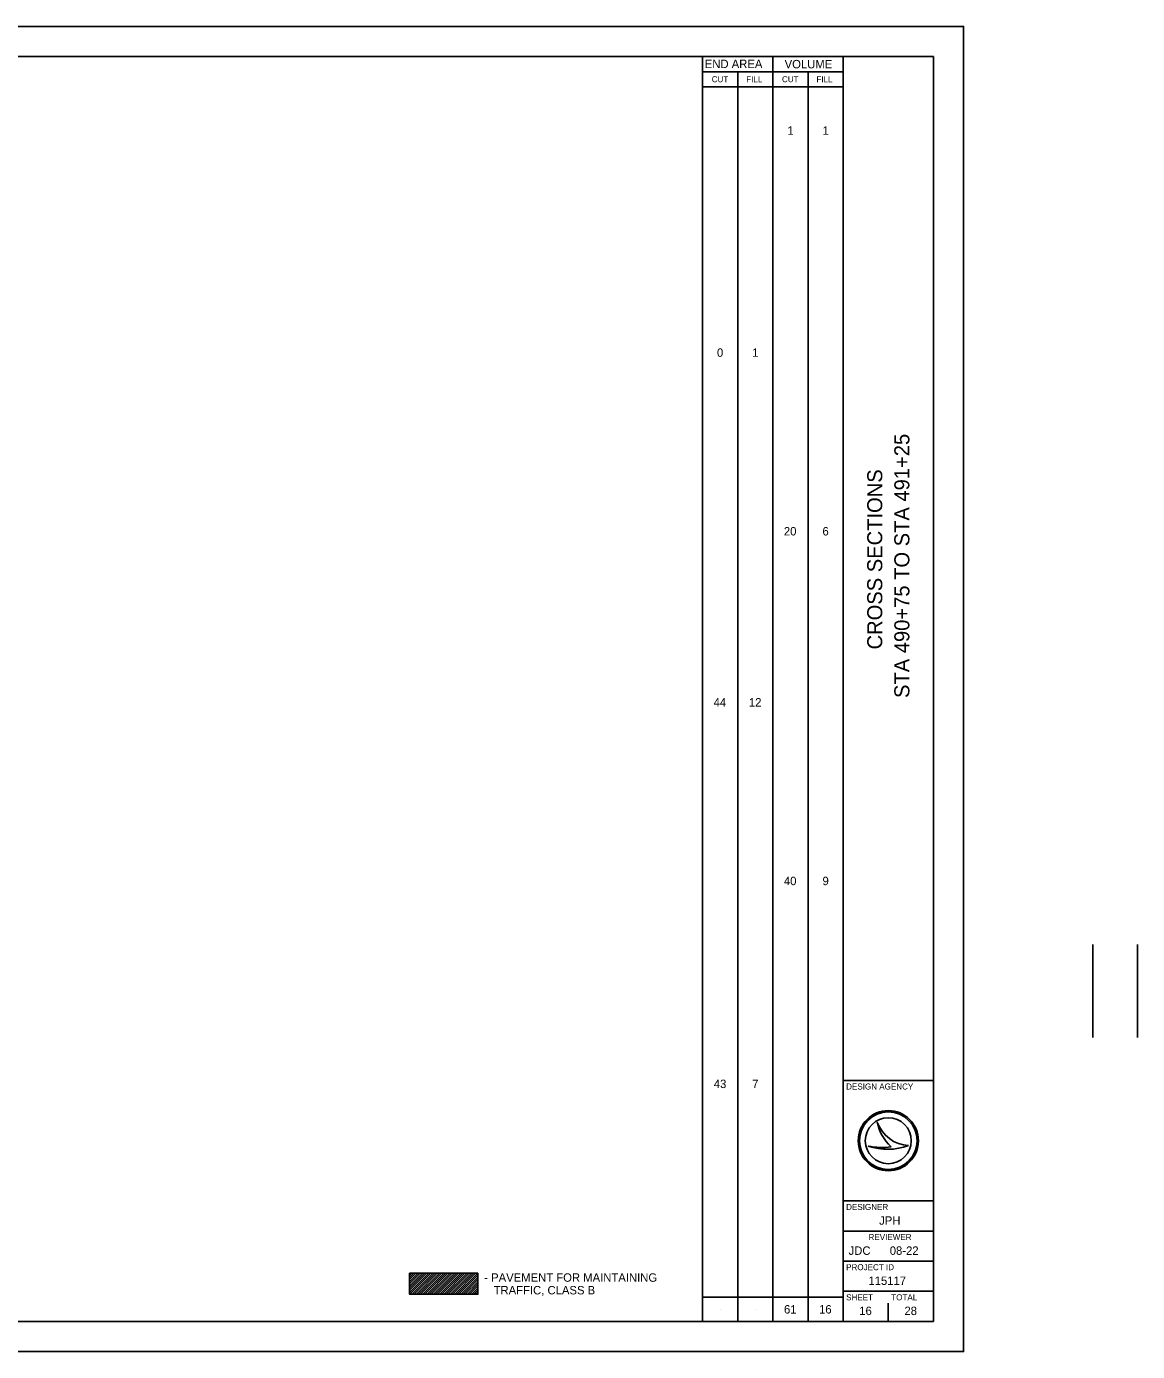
# Model space of a CAD drawing. Extents: x -78 to 37, y -177 to 22.
# Drawn here: x 18.44 to 36.89, y 0 to 22 of the extents above; entities that cross this region are included whole.
import ezdxf

# ---------------------------------------------------------------- set-up
doc = ezdxf.new("R2010")
doc.units = 0
for name, color, linetype in [('GE_X_Alignment_500_Curve_Data', 7, 'Continuous'), ('RW_P_Esmt_SH', 7, 'Continuous'), ('RW_X_Esmt_SH', 7, 'Continuous'), ('SH_Border', 7, 'Continuous'), ('SH_Cut_Line', 7, 'Continuous'), ('SH_Data', 7, 'Continuous'), ('TX_P_1', 7, 'Continuous'), ('TX_P_10', 7, 'Continuous')]:
    doc.layers.add(name, color=color, linetype=linetype)

msp = doc.modelspace()

# ---------------------------------------------------------------- linework, layer by layer
at = {"layer": 'RW_P_Esmt_SH'}
msp.add_line((36.143, 5.216), (36.143, 6.758), dxfattribs=at)
at = {"layer": 'RW_X_Esmt_SH'}
msp.add_line((36.887, 5.216), (36.887, 6.758), dxfattribs=at)
at = {"layer": 'SH_Border'}
for p, q in [((32, 0.5), (32, 21.5)), ((32, 4.5), (33.5, 4.5)), ((32, 2.5), (33.5, 2.5)), ((32, 2), (33.5, 2)), ((32, 1.5), (33.5, 1.5)), ((32, 1), (33.5, 1))]:
    msp.add_line(p, q, dxfattribs=at)
msp.add_lwpolyline([(1.5, 21.5), (33.5, 21.5), (33.5, 0.5), (1.5, 0.5)], close=True, dxfattribs=at)
at = {"layer": 'SH_Cut_Line'}
msp.add_lwpolyline([(0, 0), (34, 0), (34, 22), (0, 22)], close=True, dxfattribs=at)
at = {"layer": 'SH_Data'}
for p, q in [((29.666, 0.5), (29.666, 21.5)), ((30.833, 0.5), (30.833, 21.5)), ((29.666, 21.25), (32, 21.25)), ((30.25, 0.5), (30.25, 21.25)), ((31.417, 0.5), (31.417, 21.25)), ((29.666, 21), (32, 21)), ((32.567, 3.81), (32.567, 3.81)), ((32.417, 3.41), (32.417, 3.41)), ((32.75, 3.5), (32.75, 3.5)), ((33.087, 3.419), (33.087, 3.419)), ((29.666, 0.9), (32, 0.9)), ((29.958, 0.7), (29.958, 0.7)), ((30.542, 0.7), (30.542, 0.7)), ((31.125, 0.7), (31.125, 0.7)), ((31.708, 0.7), (31.708, 0.7)), ((32.375, 0.675), (32.375, 0.675)), ((32.75, 0.5), (32.75, 0.8))]:
    msp.add_line(p, q, dxfattribs=at)
for radius in [0.5, 0.477, 0.477, 0.382]:
    msp.add_circle((32.75, 3.5), radius, dxfattribs=at)
for centre, radius, start, end in [((33.116, 3.998), 0.58, 198.9257, 198.9319), ((33.347, 3.97), 0.796, 191.6379, 191.6421), ((33.116, 3.998), 0.58, 198.9319, 267.1657), ((33.347, 3.97), 0.796, 191.6421, 226.0947), ((32.739, 4.37), 1.013, 251.4576, 290.0832), ((32.648, 4.654), 1.266, 259.4964, 259.4995), ((32.739, 4.37), 1.013, 251.4527, 251.4576), ((32.648, 4.654), 1.266, 259.4995, 276.6672)]:
    msp.add_arc(centre, radius, start, end, dxfattribs=at)
at = {"layer": 'TX_P_1'}
for p, q in [((24.909, 1.299), (24.803, 1.193)), ((24.944, 1.299), (24.803, 1.158)), ((24.98, 1.299), (24.803, 1.122)), ((25.015, 1.299), (24.803, 1.087)), ((24.874, 1.299), (24.803, 1.229)), ((24.838, 1.299), (24.803, 1.264)), ((25.051, 1.299), (24.803, 1.052)), ((25.086, 1.299), (24.803, 1.016)), ((25.121, 1.299), (24.803, 0.981)), ((25.157, 1.299), (24.809, 0.951)), ((25.192, 1.299), (24.845, 0.951)), ((25.227, 1.299), (24.88, 0.951)), ((25.263, 1.299), (24.915, 0.951)), ((25.298, 1.299), (24.951, 0.951)), ((25.333, 1.299), (24.986, 0.951)), ((25.369, 1.299), (25.021, 0.951)), ((25.404, 1.299), (25.057, 0.951)), ((25.439, 1.299), (25.092, 0.951)), ((25.475, 1.299), (25.127, 0.951)), ((25.51, 1.299), (25.163, 0.951)), ((25.546, 1.299), (25.198, 0.951)), ((25.581, 1.299), (25.234, 0.951)), ((25.616, 1.299), (25.269, 0.951)), ((25.652, 1.299), (25.304, 0.951)), ((25.687, 1.299), (25.34, 0.951)), ((25.722, 1.299), (25.375, 0.951)), ((25.758, 1.299), (25.41, 0.951)), ((25.793, 1.299), (25.446, 0.951)), ((25.828, 1.299), (25.481, 0.951)), ((25.864, 1.299), (25.516, 0.951)), ((25.899, 1.299), (25.552, 0.951)), ((25.934, 1.299), (25.587, 0.951)), ((25.936, 1.265), (25.622, 0.951)), ((25.936, 1.23), (25.658, 0.951)), ((25.936, 1.194), (25.693, 0.951)), ((25.936, 1.159), (25.728, 0.951)), ((25.936, 1.124), (25.764, 0.951)), ((25.936, 1.088), (25.799, 0.951)), ((25.936, 1.053), (25.835, 0.951)), ((25.936, 1.018), (25.87, 0.951)), ((25.936, 0.982), (25.905, 0.951))]:
    msp.add_line(p, q, dxfattribs=at)
msp.add_lwpolyline([(25.936, 1.299), (24.803, 1.299), (24.803, 0.951), (25.936, 0.951)], close=True, dxfattribs=at)

# ---------------------------------------------------------------- texts
at = {"layer": 'GE_X_Alignment_500_Curve_Data'}
for s, p in [('1', (31.075, 20.202)), ('1', (31.658, 20.202)), ('0', (29.906, 16.516)), ('1', (30.492, 16.516)), ('20', (31.017, 13.549)), ('6', (31.657, 13.549)), ('44', (29.85, 10.709)), ('12', (30.436, 10.709)), ('40', (31.017, 7.743)), ('9', (31.658, 7.743)), ('43', (29.853, 4.374)), ('7', (30.491, 4.374)), ('61', (31.019, 0.63)), ('16', (31.601, 0.63))]:
    msp.add_text(s, height=0.14, dxfattribs=at).set_placement(p)
at = {"layer": 'SH_Data'}
for s, height, p in [('END AREA', 0.14, (29.703, 21.309)), ('VOLUME', 0.14, (31.029, 21.305)), ('CUT', 0.1, (29.819, 21.075)), ('FILL', 0.1, (30.391, 21.075)), ('CUT', 0.1, (30.985, 21.075)), ('FILL', 0.1, (31.557, 21.075)), ('DESIGN AGENCY', 0.1, (32.05, 4.35)), ('DESIGNER', 0.1, (32.05, 2.35)), ('JPH', 0.14, (32.598, 2.105)), ('REVIEWER', 0.1, (32.422, 1.85)), ('JDC', 0.14, (32.091, 1.605)), ('08-22', 0.14, (32.774, 1.605)), ('PROJECT ID', 0.1, (32.05, 1.35)), ('115117', 0.14, (32.42, 1.105)), ('SHEET', 0.1, (32.05, 0.85)), ('TOTAL', 0.1, (32.8, 0.85)), ('16', 0.14, (32.268, 0.605)), ('28', 0.14, (33.018, 0.605))]:
    msp.add_text(s, height=height, dxfattribs=at).set_placement(p)
for s, p in [('STA 490+75 TO STA 491+25', (33.1, 10.851)), ('CROSS SECTIONS', (32.65, 11.657))]:
    msp.add_text(s, height=0.25, rotation=90, dxfattribs=at).set_placement(p)
at = {"layer": 'TX_P_10'}
for s, p in [('- PAVEMENT FOR MAINTAINING', (26.042, 1.158)), ('   TRAFFIC, CLASS B', (26.042, 0.948))]:
    msp.add_text(s, height=0.14, dxfattribs=at).set_placement(p)

doc.saveas('drawing.dxf')
